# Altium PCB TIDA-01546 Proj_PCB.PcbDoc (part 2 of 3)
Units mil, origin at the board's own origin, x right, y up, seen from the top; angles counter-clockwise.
Board outline 2500 x 2000 mil, 2 copper layers (Top Layer, Bottom Layer), stack 62 mil thick; 176 components, 113 nets, 564 pads, 250 vias.
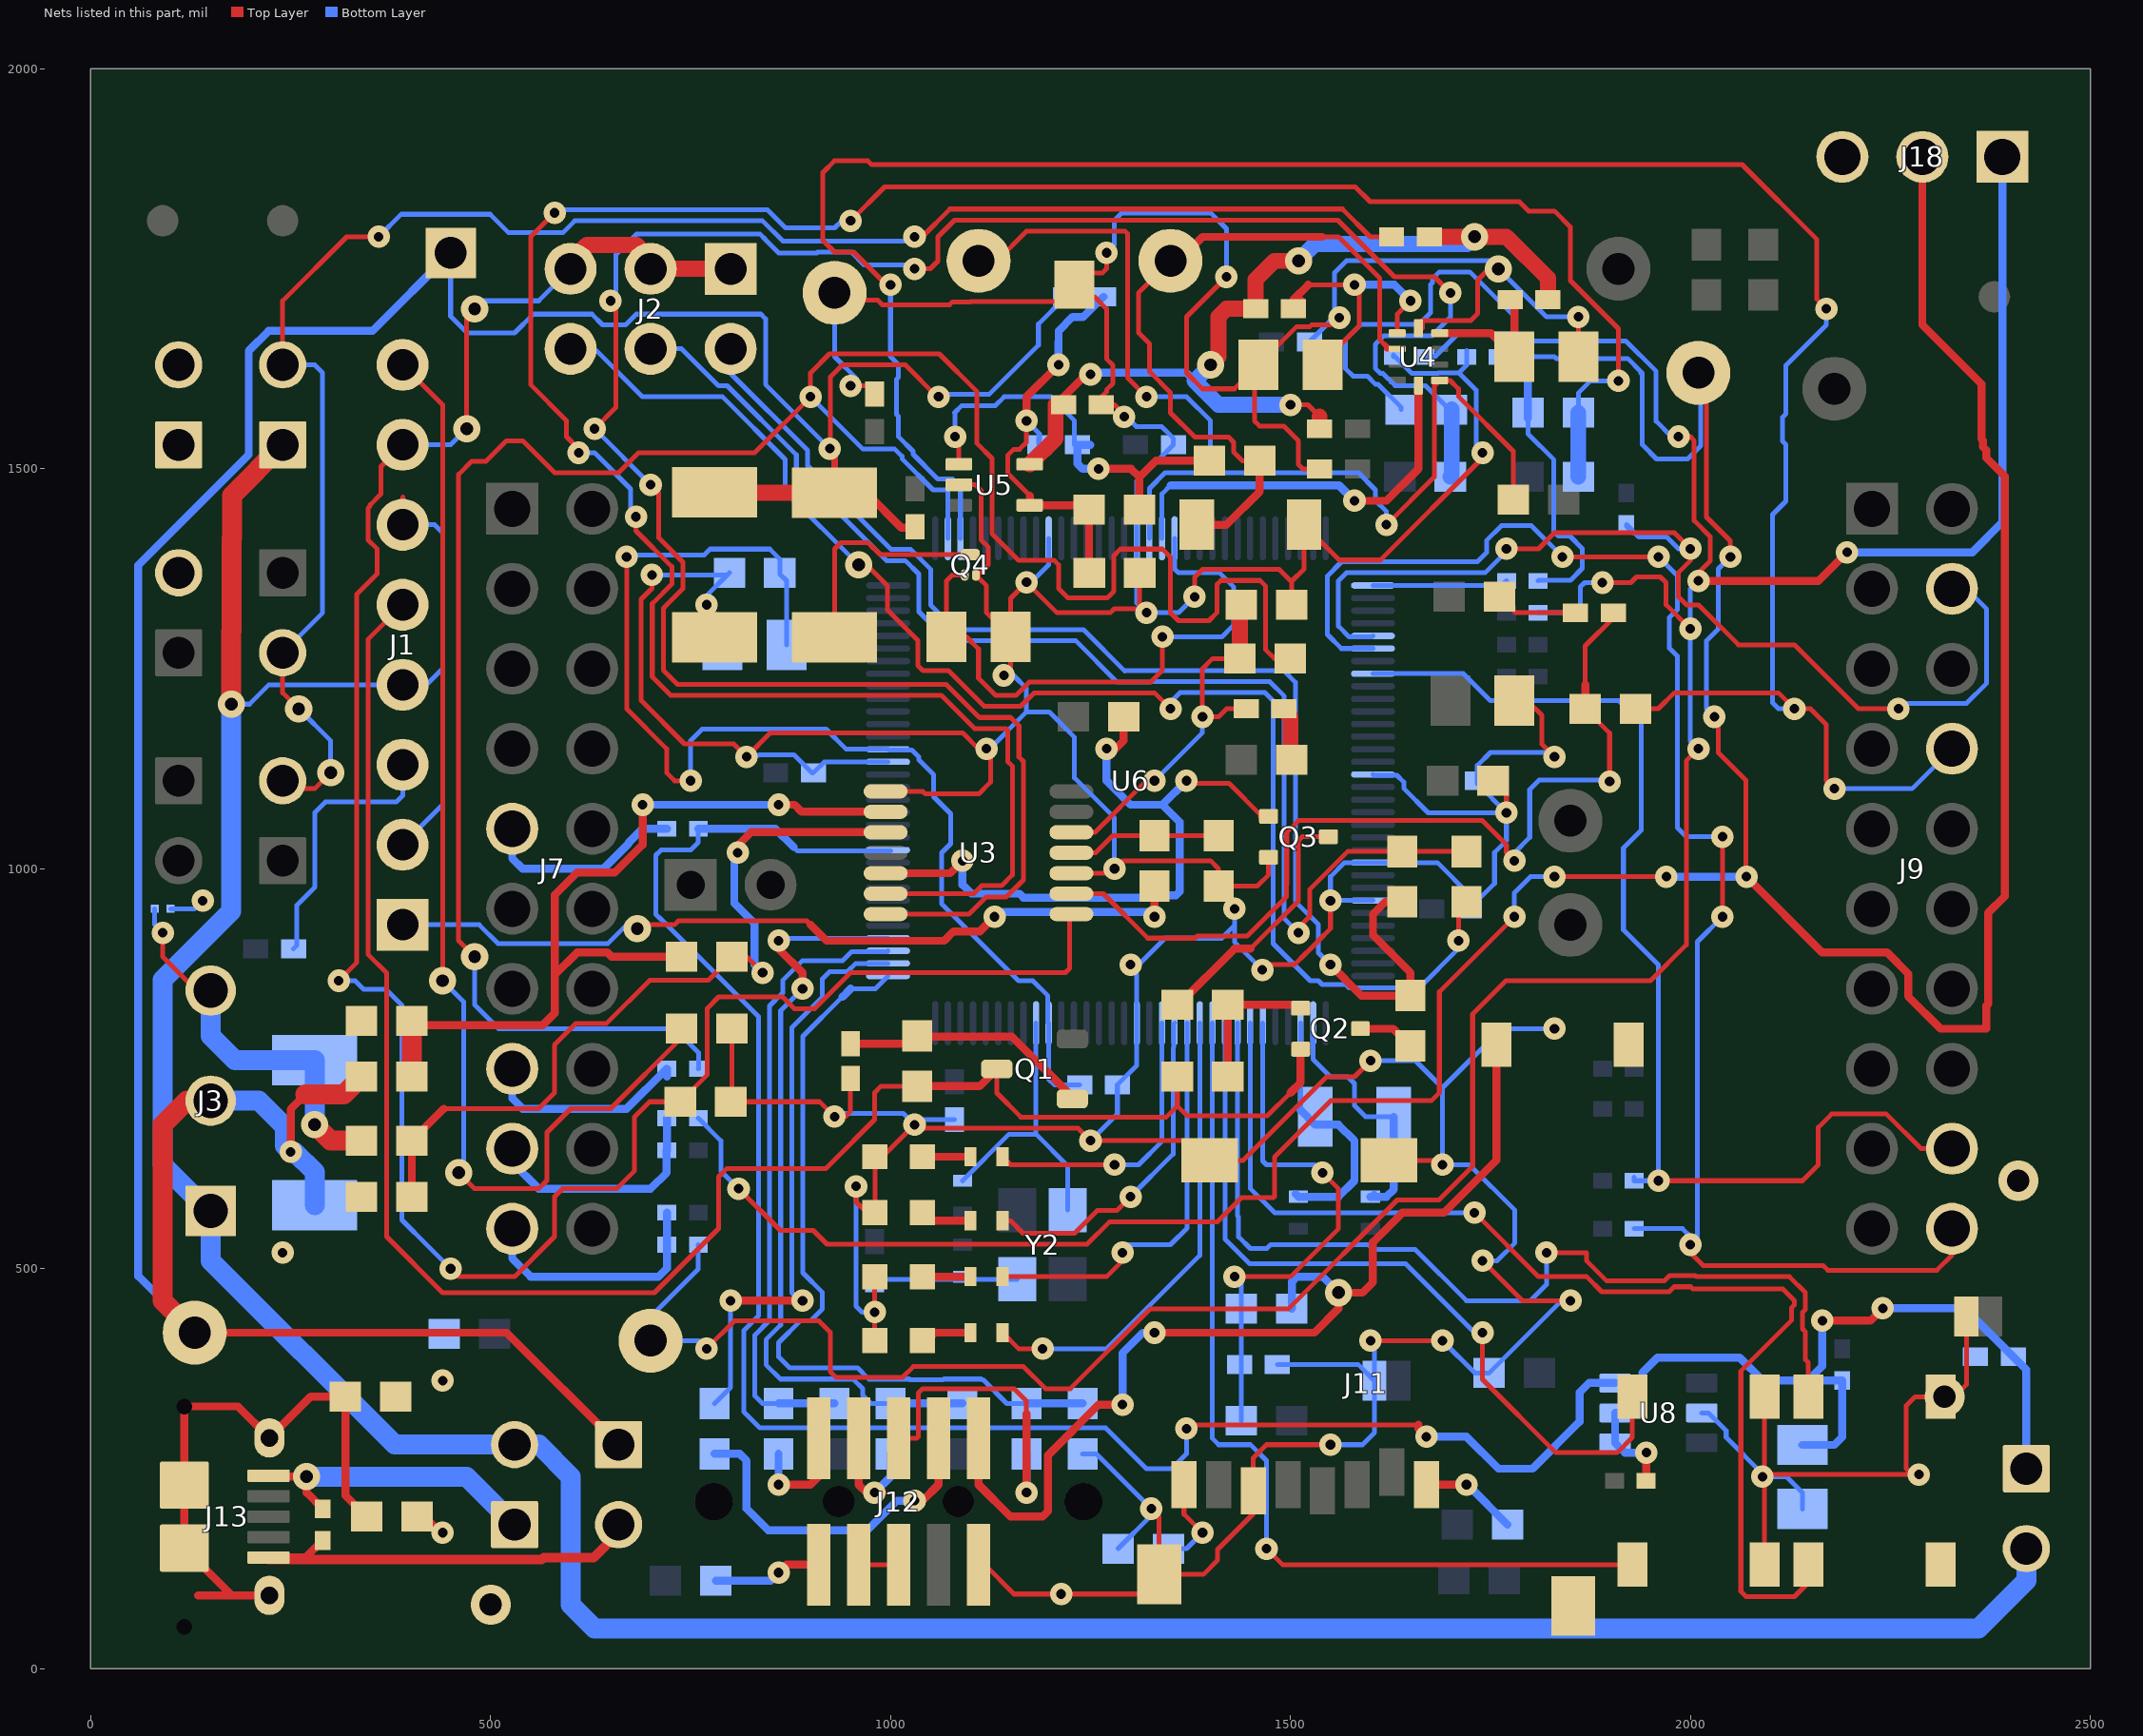
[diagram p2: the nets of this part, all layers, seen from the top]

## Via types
v1: diameter 28, hole 12, Top Layer to Bottom Layer, 217 vias
v2: diameter 34, hole 16, Top Layer to Bottom Layer, 30 vias
v3: diameter 50, hole 28, Top Layer to Bottom Layer, 3 vias

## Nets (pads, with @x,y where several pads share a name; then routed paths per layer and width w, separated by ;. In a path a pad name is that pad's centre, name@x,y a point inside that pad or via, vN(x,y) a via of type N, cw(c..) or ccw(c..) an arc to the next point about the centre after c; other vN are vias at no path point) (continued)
AGND: C8.1 C10.1 NT2.1 R35.2 R77.1 U4.10 | length 1552.6
  Top Layer w6: NT2.1@1230,1745 1265,1745 1270,1750 v1(1270,1770) v1@1265,1765 ; v1(1420,1740) 1370,1690 1370,1620 1390,1600 1430,1600 C8.1@1455.13,1625.13 ; R35.2@1536.38,1500 1515.17,1500 1510,1505.17 1510,1533.2 1509.76,1533.44 1509.76,1535.12 1491.43,1553.45 1461.37,1553.45 1455.13,1559.7 C8.1@1455.13,1625.13 ; v1(1561.14,1688.86) 1560,1690 1550.18,1680.18 1526.74,1680.18 1523.87,1677.32 1507.32,1677.32 C8.1@1460,1630 C8.1@1455.13,1625.13 ; U4.10@1660,1675.93 1664.87,1675.93 1664.87,1685.4 1725.4,1685.4 1734.07,1694.07 1734.07,1735.93 1748.13,1750 v2(1760,1750) ; C10.1@1860,1640 v1(1860,1690)
  Bottom Layer w6: v1(1270,1770) 1280,1780 1280,1810.87 1289.13,1820 1400,1820 1420,1800 v1(1420,1740) ; R77.1@1523.62,1658.52 1553.96,1688.86 v1(1561.14,1688.86) 1555.13,1694.87 1555.13,1745.13 1570,1760 1750,1760 v2(1760,1750) 1820,1690 v1(1860,1690)
ALERT: R26.2 TP10.1 U4.6 U6.18 | length 1390
  Top Layer w6: TP10.1@1110,1760 1133,1760 1170,1797 1293,1797 1296.13,1793.87 1296.13,1613.87 v1(1320,1590) ; v1(1620,1430) 1680,1490 1680,1603.9 U4.6@1686.57,1610.47 1699.53,1610.47 1710,1600 1710,1590.38 1778.5,1521.88 R26.2@1778.5,1461.46 R26.2@1780,1462.95
  Bottom Layer w6: v1(1320,1590) 1370,1590 1400,1560 1400,1495.17 ; U6.18@1323.62,1413.15 1323.62,1475.36 1343.42,1495.17 1400,1495.17 ; v1(1620,1430) 1620,1446.72 1606.29,1460.43 1606.29,1473.71 1584.83,1495.17 1400,1495.17
AVDD: C9.1 R24.2 R27.2 R34.1 R58.2 U5.5 | length 1144.2
  Top Layer w6: v1(1500,1580) 1521.65,1580 1536.38,1565.28
  Top Layer w10: C9.1@1206.38,1580 1244.5,1618.13 v1(1250,1618.13)
  Top Layer w20: U5.5@1173.98,1505.59 1206.38,1537.99 C9.1@1206.38,1580 ; v2(1400,1630) 1410,1640 1410,1690 1420,1700 R58.2@1456.38,1700 1456.38,1736.38 1480,1760 v2(1510,1760) ; R34.1@1536.38,1550 1536.38,1565.28 ; R24.2@1673.62,1790 v2(1730,1790) 1770,1790 1821.85,1738.15 R27.2@1821.85,1711.34
  Bottom Layer w10: v1(1250,1618.13) 1252.13,1620.25 1369.75,1620.25 1380,1610
  Bottom Layer w20: v2(1400,1630) 1380,1610 1410,1580 v1(1500,1580) ; v2(1510,1760) 1530.87,1780.87 1720.87,1780.87 v2(1730,1790)
B\U\S\Y/RDY: U4.5 U6.19 | length 509.2
  Top Layer w10: v1(1580,1460) 1620,1460 1660,1500 U4.5@1660,1604.07
  Bottom Layer w6: U6.19@1339.37,1413.15 1339.37,1468.66 1350,1479.29
  Bottom Layer w10: 1350,1479.29 1560.71,1479.29 v1(1580,1460)
BAT+: J1.2 J1.4 J1.6 J3.1 J4.1 J14.2 J20.2 | length 4532
  Top Layer w6: J4.1@230,1530 J4.1@240,1530 ; J1.6@390,1430 390,1464.42
  Top Layer w25: J3.1@150,560 J3.1@150,572.2 ; v2(175.75,1205.75) 175.75,1296.82 176.22,1297.29 176.22,1412.9 176.63,1413.31 176.63,1466.63 J4.1@240,1530
  Bottom Layer w6: v2(175.75,1205.75) 198.62,1205.75 222.86,1230 223.27,1229.6 390,1229.6 J1.4@390,1230 420,1230 440,1250 ; J1.2@390,1030 440,1080 440,1250 ; J1.6@390,1430 430,1430 440,1420 440,1250
  Bottom Layer w25: v2(175.75,1205.75) 175.75,946.9 90,861.15 90,630 147.8,572.2 J3.1@150,572.2 150,510 380,280 J14.2@530,280 560,280 600,240 600,80 630,50 2360,50 2420,110 J20.2@2420,150
BAT-: J3.2 J8.1 J15.1 R17.1 R19.1 R32.1 R33.1 R90.1 R93.1 TP8.1 | length 4427.8
  Top Layer w6: v1(924,1525.13) 924.87,1526 924.87,1614.87 939.74,1629.74 1018.59,1629.74 1058.34,1590 v1(1060,1590)
  Top Layer w8: R33.1@930,1470.24 v1@930,1520.32
  Top Layer w10: TP8.1@130,420 520,420 J15.1@660,280 ; v1(250,646.03) 250,699.26 268.61,717.87 ; R33.1@930,1470 969.94,1470 1013.56,1426.38 R90.1@1020,1426.38
  Top Layer w20: R32.1@780,1470.55 780.55,1470 R33.1@930,1470
  Top Layer w25: TP8.1@130,420 90,460 90,680 120,710 J3.2@150,710 J3.2@150,700 ; 268.61,717.87 316.38,717.87 R17.1@338.5,740
  Bottom Layer w6: J8.1@450,1770 450,1690.58 470.63,1669.95 529.91,1669.95 553.31,1693.35 626.65,1693.35 640,1680 668.69,1680 682.04,1693.35 837.83,1693.35 843.66,1687.52 843.66,1605.46 v1(924,1525.13) ; v1(1060,1590) 1063,1593 1123.18,1593 1184.87,1654.7 1184.87,1681 R93.1@1218.88,1715
  Bottom Layer w10: TP8.1@130,420 59.45,490.55 59.45,1379.45 197.6,1517.6 197.6,1647.56 222.44,1672.4 352.4,1672.4 J8.1@450,1770
  Bottom Layer w25: J3.2@150,710 210,710 242.63,677.37 242.63,653.41 v1(250,646.03) 254.79,646.03 280,620.82 R19.1@280,579.45
BQ_ALERT: J9.8 R16.2 U6.3 | length 3009.5
  Top Layer w6: v1(1000,1730) 994.82,1730 953.95,1770.87 930,1770.87 915.26,1785.62 915.26,1849.44 915.13,1849.57 915.13,1870.3 929.7,1884.87 971.59,1884.87 976.22,1880.24 2064.66,1880.24 2157.75,1787.15 2157.75,1712.25 v1(2170,1700) ; R16.2@1931.5,1200 1960,1200 1980,1220 2110,1220 v1(2130,1200) 2150,1200 2170,1180 2170,1110 v1(2180,1100)
  Bottom Layer w6: v1(1000,1730) 1000,1640 1010,1630 1010,1614.42 1007.38,1611.8 1007.38,1568.2 1010,1565.58 1010,1540 1028.17,1521.83 1028.17,1518.2 1058.99,1487.38 1077.43,1487.38 1087.4,1477.4 U6.3@1087.4,1413.15 ; v1(2130,1200) 2110,1200 2102.62,1207.38 2102.62,1442.62 2119.26,1459.26 2119.26,1530.36 2115.13,1534.49 2115.13,1564.44 2119.26,1568.58 2119.26,1629.26 2170,1680 v1(2170,1700) ; v1(2180,1100) 2277,1100 J9.8@2327,1150
BQ_SCL: J18.2 R7.2 R37.1 R46.1 TP5.1 U2.1 | length 4751.6
  Top Layer w6: v1(810,600) 862.25,547.75 903.38,547.75 920.63,530.5 1245.7,530.5 1273.95,558.75 1408.75,558.75 1438.75,588.75 1478.75,588.75 1480,590 1480,639.62 1550.38,710 1676.13,710 1686.13,720 1686.13,846.13 v1(1780,940) ; v1(1830,990) v1(1970,990) ; TP5.1@2010,1620 2020,1610 2020,1439.62 2049.62,1410 2049.62,1390.38 v1(2050,1390) ; v1(2030,1190) 2034.87,1185.13 2034.87,1145.13 2069.24,1110.76 v1@2069.24,990
  Top Layer w10: v1@2069.24,990 v1(2070,990) 2164.65,895.35 2245.79,895.35 2272.35,868.79 2272.35,840.51 2312.86,800 2370,800 2370,828.86 2372.35,831.21 2372.35,944.91 2392.87,965.42 2392.87,1490.76 2370,1513.64 2370,1523.2 2365.69,1527.5 2365.69,1535.45 2363.78,1537.36 2363.78,1606.22 2290,1680 J18.2@2290,1890
  Bottom Layer w6: R46.1@759.68,688.19 787.87,660 787.87,622.13 v1(810,600) ; U2.1@1759.68,1640 1770,1640 1830,1640 1832.13,1637.87 1921.55,1637.87 1937.87,1621.55 ; v1(1780,940) 1780,970 1800,990 v1(1830,990) ; R7.2@1796.85,1563.15 1796.85,1543.76 1829.28,1511.33 1829.28,1421.49 1834.87,1415.9 1849.28,1415.9 1864.87,1400.3 1864.87,1375.4 1850,1360.52 1810.21,1360.52 R37.1@1809.68,1360 ; 1937.87,1619.42 1937.87,1621.55 ; TP5.1@2010,1620 2012.87,1620 2012.87,1528.68 1996.55,1512.35 1957.65,1512.35 1940,1530 1940,1619.42 1937.87,1621.55 ; v1(2030,1190) 2020,1200 2020,1284.82 2034.87,1299.7 2034.87,1374.87 v1(2050,1390)
  Bottom Layer w10: U2.1@1770,1640 1796.85,1613.15 R7.2@1796.85,1570 R7.2@1796.85,1563.15 ; v1(1970,990) v1@2060,990
BQ_SDA: J18.1 R6.2 R38.2 R47.1 TP4.1 U1.1 | length 4552.6
  Top Layer w6: v1(770,400) 804.87,434.87 910.3,434.87 924.87,420.3 924.87,371.06 932.06,363.87 1014.63,363.87 1028.36,377.6 1166.07,377.6 1193.67,350 1224.82,350 1324.82,450 1497.55,450 1633.42,585.87 1685.42,585.87 1727.75,628.2 1727.75,818.43 1769.31,860 1950,860 1994.87,904.87 1994.87,1134.87 v1(2010,1150) ; v1(1890,1357.7) 1925.4,1357.7 1932.58,1364.87 1962.35,1364.87 1969.65,1357.58 1969.65,1329.9 1999.54,1300 v1(2000,1300) ; v1(1985,1540.23) 1999.77,1540.23 2004.71,1535.29 2004.71,1435.29 2024.87,1415.13 2024.87,1384.82 2010,1369.95 v1(2010,1360)
  Top Layer w10: v1(2010,1360) 2160.13,1360 v1(2195.78,1395.65)
  Bottom Layer w6: R47.1@759.68,530 759.68,499.68 700,440 TP4.1@700,410 760,410 v1(770,400) ; R6.2@1638.5,1574 1638.5,1576.67 1609.77,1605.41 1606.46,1605.41 1596,1615.87 1578.13,1615.87 1568.54,1625.46 1568.54,1661.08 1587.82,1680.35 1660.35,1680.35 1675.13,1695.13 1675.13,1730.3 1677.41,1732.59 1677.41,1737.41 1686.13,1746.13 1724.1,1746.13 1780,1690.23 1780,1668.54 ; U1.1@1668.03,1640 1680.51,1640 1709.06,1668.54 1780,1668.54 ; R38.2@1809.69,1320 1856.38,1320 1862.28,1325.91 1862.28,1352.28 1867.7,1357.7 v1(1890,1357.7) ; v1(1985,1540.23) 1976.45,1540.23 1957.13,1559.55 1957.13,1621.91 1919.04,1660 1788.54,1660 1780,1668.54 ; v1(2010,1150) 2000,1160 v1(2000,1300) 2000,1350 v1(2010,1360)
  Bottom Layer w10: v1(2195.78,1395.65) 2352.66,1395.65 2390,1432.98 J18.1@2390,1890
BUT_S1: S1.2 U6.74 | length 1173.8
  Top Layer w6: v1(1470,150) 1490,130 S1.2@1927.32,130
  Bottom Layer w6: U6.74@1402.36,806.85 1402.36,287.8 1410.16,280 1450,280 1470,260 v1(1470,150)
BUT_S2: S2.2 U6.73 | length 982.7
  Top Layer w6: v1(1740,420) 1740,361.65 1831.65,270 1908.4,270 1927.32,288.93 S2.2@1927.32,340
  Bottom Layer w6: U6.73@1418.11,806.85 1418.11,537.07 1449.05,506.13 1643.87,506.13 1730,420 v1(1740,420)
BUT_S3: S3.2 U6.72 | length 1228
  Top Layer w6: v1(1820,520) 1870,520 1870,510 1895,485 1967.7,485 1973.95,491.25 2006.05,491.25 2007.3,490 2123.87,490 2143.87,470 2143.87,449.05 2140.13,445.3 2140.13,424.7 2143.87,420.95 2143.87,386.13 2147.32,382.68 S3.2@2147.32,340
  Bottom Layer w6: U6.72@1433.86,806.85 1433.86,566.14 1435.13,564.87 1435.13,539.7 1449.7,525.13 1470.3,525.13 1475.18,530 1597.55,530 1603.43,524.13 1655.87,524.13 1720,460 1800,460 1820,480 v1(1820,520)
BUT_S4: S4.2 U6.71 | length 1458.2
  Top Layer w6: v1(1730,570) 1810,490 1870.38,490 1889.25,471.13 1973.45,471.13 1979.7,477.37 2000.3,477.37 2002.8,474.87 2115.13,474.87 2130,460 2130,454.8 2126.25,451.05 2126.25,435.21 2063.1,372.06 2063.1,96.47 2069.58,90 2130,90 2147.32,107.32 S4.2@2147.32,130
  Bottom Layer w6: U6.71@1449.61,806.85 1449.61,600.39 1480,570 v1(1730,570)
D\E\B\U\G\_\R\E\S\E\T\: J12.P10 R70.2 RESET1.2 | length 1273.4
  Top Layer w10: J12.P10@1110,287.8 1110,230 1150,190 1190,190 1196.87,196.87 1196.87,266.87 1260,330 v1(1290,330) ; v1(1330,420) 1530,420 1560,450 v2(1560,470) 1590,470 1603.13,483.13 1603.13,533.13 1640,570 1691.99,570 1757.32,635.33 RESET1.2@1757.32,780
  Bottom Layer w10: v1(1290,330) 1290,394.4 1315.6,420 v1(1330,420) ; R70.2@1501.5,450 1501.89,450.39 1501.89,483.7 1508.19,490 1540,490 v2(1560,470)
DEBUG_TCK: R43.2 R50.2 U6.100 | length 970.2
  Top Layer w10: v1(860,910) 860,900 890,870 v1(890,850)
  Bottom Layer w6: v1(860,910) 863.15,913.15 U6.100@996.85,913.15 ; v1(890,850) 862.62,822.62 862.62,429.65 844.31,411.33 844.31,380 862.25,362.06 953.14,362.06 965.19,350 965.19,341.61 975.3,331.5 R50.2@1000,331.5
  Bottom Layer w10: R50.2@1000,331.5 R43.2@1090,331.5
DEBUG_TDI: R53.2 U6.98 | length 742.7
  Top Layer w10: v1(800,460) v1(890,460)
  Bottom Layer w6: R53.2@780,331.5 800,351.5 v1(800,460) ; v1(890,460) 886.5,460 876.5,470 876.5,801.32 914.87,839.7 914.87,862.42 923.7,871.25 946.05,871.25 956.45,881.65 U6.98@996.85,881.65
DEBUG_TDO: R51.2 R56.1 U6.97 | length 983.5
  Bottom Layer w6: 940,840 890.37,790.37 890.37,494.81 914.87,470.3 914.87,449.7 900.3,435.13 887.72,435.13 860,407.4 860,390 874.07,375.93 958.89,375.93 972.76,362.06 1023.2,362.06 1024.24,361.02 1065.76,361.02 1066.8,362.06 1113.2,362.06 1114.24,361.02 1115.78,361.02 1145.3,331.5 R51.2@1170,331.5 ; 950,850 980.94,850 U6.97@996.85,865.91
  Bottom Layer w10: 940,840 950,850 ; R51.2@1170,331.5 R56.1@1240,331.5
DEBUG_TMS: R42.2 R49.2 U6.99 | length 784.2
  Bottom Layer w6: R49.2@859.93,331.5 839.89,331.5 830.43,340.96 830.43,417.08 848.75,435.39 848.75,828.37 865.13,844.75 865.13,860.3 889.95,885.13 940.3,885.13 951.64,896.46 995.91,896.46 U6.99@996.85,897.4
  Bottom Layer w10: R49.2@859.93,331.5 R42.2@929.93,331.5
GE: R22.2 R52.1 U6.2 | length 2930.7
  Top Layer w6: v2@483.65,893.65 v2(480,890) 460,910 460,1493 476.43,1509.43 494.25,1509.43 519.7,1534.87 540.3,1534.87 580.05,1495.13 660,1495.13 684.87,1520 830,1520 v1(900,1590) 900,1620 923.62,1643.62 1060.98,1643.62 1108.13,1596.47 1108.13,1531.72 1126.87,1512.97 1126.87,1418.72 1160,1385.59 1204.41,1385.59 1210,1380 1210,1350.43 1221.69,1338.75 1271.02,1338.75 1279.06,1346.8 1279.06,1391.33 1287.31,1399.57 1339.98,1399.57 1350,1389.56 1350,1320 1360,1310 1397.94,1310 1407.94,1320 1407.94,1355.19 1413.09,1360.34 1461.93,1360.34 1469.06,1353.2 1469.06,1273.62 1480,1262.68 R22.2@1499.84,1262.68
  Bottom Layer w6: v2(480,890) 480,830 510,800 730,800 760,770 760,750.32 R52.1@759.68,750 ; v1(900,1590) 965,1525 1004.84,1525 1014.13,1515.71 1014.29,1515.71 1014.29,1512.46 1053.24,1473.5 1071.65,1473.5 U6.2@1071.65,1413.15
GND: C1.2 C2.1 C4.1 C5.1 C6.1 C7.1 C9.2 C11.1 C13.1 C14.1 C15.1 C16.1 C17.1 C18.1 C19.1 C22.1 C23.1 C24.1 C27.1 D1.2 J10.2 J11.6 J11.S1 J11.S2 J11.S3 J11.S4 J12.P3 J12.P5 J12.P9 J17.1 J17.2 J18.3 LED1.2 LED2.2 LED3.2 LED4.2 NT1.2 NT2.2 NT3.2 NT4.1 Q3.2 Q4.2 R9.2 R23.2 R28.1 R32.2 R36.2 R56.2 R67.2 R71.2 R74.2 R92.1 R94.1 R95.1 RESET1.1 S1.1 S2.1 S3.1 S4.1 TP3.1 U1.2 U2.2 U3.3 U3.8 U5.2 U6.10 U6.17 U6.48 U6.55 U6.58 U6.80 U6.114 U8.2 | length 10875.4
  Top Layer w6: R74.2@420,190 v1(440,170) ; v1(701.75,1367.31) 701.75,1350.65 689.26,1338.16 689.26,1337.97 688.23,1336.94 688.23,1222.1 688,1221.87 688,1210.38 742.25,1156.13 803.87,1156.13 v1(820,1140) 849.95,1169.95 1090.05,1169.95 1110,1150 v1(1120,1150) 1124.87,1145.13 1124.87,1108.11 1110.3,1093.54 1043.54,1093.54 1040.32,1096.76 U3.8@993.85,1096.76 ; v1@764.49,1335.43 v1@769.92,1330 ; v1(770,1330) v1@769.92,1330 ; R32.2@780,1289.45 780,1319.92 v1@769.92,1330 ; R9.2@801.5,800 801.5,710 C1.2@800.2,708.7 911.3,708.7 v1(930,690) 943.24,690 950,696.76 D1.2@950,738.03 ; TP3.1@930,1720 960,1720 969.13,1710.87 983.95,1710.87 989.7,1705.13 1073.76,1705.13 1077.38,1708.75 1099.62,1708.75 1100,1709.13 1224.13,1709.13 NT2.2@1230,1715 1255,1715 1270,1700 1270,1637.55 1277.87,1629.67 1277.87,1606.58 1270,1598.71 1270,1596.38 1253.62,1580 1280,1580 1292.11,1567.89 v1(1292.11,1565) ; v1(950,1603.62) 970,1603.62 R92.1@980,1593.62 ; v1(956.85,603) 956.85,583.6 970.45,570 LED2.2@980.47,570 LED1.2@980.47,640 990,640 v1(1030,680) 1034.28,675.72 1234.28,675.72 v1(1250,660) 1374.25,660 J11.S3@1398.74,635.51 1440.87,635.51 1545.35,740 1580,740 v1(1600,760) ; J12.P3@960,130 J12.P5@1010,130 ; LED4.2@980.47,410 980.17,410.3 v1(980.17,445.63) 980.17,489.7 LED3.2@980.47,490 ; U5.2@1085.39,1480 1106.16,1480 1113,1473.16 1113,1411.26 1122.37,1401.89 1122.37,1380.09 1109.49,1367.2 1109.49,1364.29 1120,1353.78 1120,1320 R36.2@1150,1290 ; J12.P9@1110,130 1117.64,130 1154.35,93.28 v1(1213.22,93.28) 1311.24,93.28 J11.S2@1335.75,117.8 ; v1@1150,1250 R36.2@1150,1290 ; U3.3@1226.13,994.4 1274.4,994.4 v1(1280,1000) 1290,1010 1400,1010 1410,1000 C2.1@1410,978.5 ; v1@1311.5,1328.5 R28.1@1311.5,1370 ; v1(1320,1320) 1315.13,1324.87 1279.7,1324.87 1274.82,1320 1208.03,1320 v1(1170,1358.03) 1150,1338.03 R36.2@1150,1290 ; v1(1325.9,200) 1335.75,190.15 1335.75,122.8 1340.75,117.8 1391.07,117.8 1408.88,135.61 1408.88,148.88 1453.46,193.46 J11.6@1453.46,222.13 1453.46,263.46 1470,280 v1(1550,280) ; v1(1380,1340) 1380,1364.34 1389.87,1374.22 1485.78,1374.22 1500.65,1359.35 1501.5,1359.35 ; v1@1431.02,957.48 C2.1@1410,978.5 ; v1(1464.83,873.53) 1464.83,874.83 1470,880 1504.82,880 1519.95,895.13 1520.3,895.13 1534.87,909.7 1534.87,910.05 1550,925.18 v1(1550,960) ; Q3.2@1472.6,1014.41 1472.6,992.36 1458.74,978.5 C2.1@1410,978.5 ; R23.2@1501.5,1330 1501.5,1359.35 ; v1(1600,410) v1(1690,410) ; J11.S4@1623.15,635.51 1684.49,635.51 v1(1690,630) ; v1(1740,510) 1790,460 v1(1850,460) ; v1(1740,1520) 1740,1513.42 1612.51,1385.93 1561,1385.93 C11.1@1516.93,1430 1516.93,1374.78 1501.5,1359.35 ; C7.1@1753.31,1110 1770,1093.31 v1(1770,1070) ; C4.1@1780,1210 1796.13,1210 1814.43,1191.69 1814.43,1155.57 v1(1830,1140) ; S1.1@2092.68,130 2092.68,237.32 v1(2090,240) v1@2092.68,242.68 ; S2.1@2092.68,340 v1@2092.68,242.68 ; v1(2285.56,242.68) v1@2277.32,242.68 ; NT4.1@2345,440 2345,355 2330,340 S3.1@2312.68,340 2281.07,340 2270,328.93 2270,250 v1@2277.32,242.68 ; v1@2092.68,242.68 v1@2277.32,242.68
  Bottom Layer w6: NT1.2@100,950 130,950 v1(140,960) ; v1(701.75,1367.31) C22.1@795.81,1367.31 ; C23.1@790,1280 770,1300 v1(770,1330) 770,1341.5 C22.1@795.81,1367.31 ; C22.1@798.5,1370 C22.1@795.81,1367.31 ; v1(820,1140) 821.65,1141.65 835.09,1141.65 836.13,1142.68 878.97,1142.68 901.65,1120 C18.1@903.62,1120 917.24,1133.62 U6.114@996.85,1133.62 ; v1(930,690) 934.12,694.12 1015.88,694.12 v1(1030,680) 1036.38,686.38 C17.1@1080,686.38 ; TP3.1@930,1720 930,1640 958.19,1611.81 v1(950,1603.62) ; v1(956.85,603) 956.85,453.15 964.37,445.63 v1(980.17,445.63) ; v1(1120,1150) 1123.9,1150 1170,1196.1 ; v1(1141.61,1241.76) 1153.79,1241.76 1170,1225.55 1170,1196.1 ; v1(1170,1358.03) 1175.67,1358.03 1197.64,1380 U6.10@1197.64,1413.15 ; R56.2@1240,268.5 1257.4,268.5 v1(1325.9,200) 1325.9,191.5 R67.2@1284.41,150 ; v1(1250,660) 1283.62,693.62 C24.1@1283.62,730 1307.87,754.25 U6.80@1307.87,806.85 1307.87,867.95 v1@1295.82,880 ; v1(1280,1000) 1280,1063.54 1230,1113.54 1230,1164.27 1198.17,1196.1 1170,1196.1 ; v1(1292.11,1565) 1295,1565 1307.32,1552.68 1338.97,1552.68 1353.62,1538.03 C15.1@1353.62,1530 1307.87,1484.25 U6.17@1307.87,1413.15 1307.87,1332.13 v1(1320,1320) 1360,1320 v1(1380,1340) ; v1@1292.89,882.93 v1@1295.82,880 ; v1(1430,950) 1430,929.18 ; v1(1464.83,873.53) 1430,908.35 1430,929.18 ; C13.1@1483.62,380 1585,380 NT3.2@1605,360 ; v1(1550,280) 1590,280 1605,295 NT3.2@1605,360 ; v1@1599.03,759.03 v1(1600,760) 1656.13,760 1690,726.13 ; v1(1600,410) 1605,405 NT3.2@1605,360 ; U6.58@1603.15,960.39 1550.39,960.39 v1(1550,960) 1550,990 1567.64,1007.64 U6.55@1603.15,1007.64 1683.66,1007.64 1723.62,967.68 R71.2@1723.62,950 1755.13,981.5 1755.13,1020.3 1770,1035.18 v1(1770,1070) ; U6.48@1603.15,1117.87 1604.09,1116.94 1632.91,1116.94 1641.58,1108.26 1641.58,1100.66 1672.24,1070 v1(1770,1070) ; U1.2@1628.66,1642.44 U1.2@1628.66,1640 1631,1640 1651.72,1619.28 1684.35,1619.28 1685.06,1620 1710.63,1620 ; v1(1690,410) 1730.32,369.68 C19.1@1748.5,369.68 1838.82,460 v1(1850,460) ; U2.2@1720.32,1648.03 U2.2@1720.32,1640 1720.32,1629.68 1710.63,1620 ; v1(1740,510) 1758.48,510 1780.6,532.13 1780.6,573.13 1723.73,630 v1(1690,630) 1690,726.13 ; v1(1740,1520) 1732.06,1527.94 1732.06,1598.57 1710.63,1620 ; v1(1830,800) 1763.87,800 1690,726.13 ; v1(1830,1140) 1824.5,1145.5 1750,1145.5 1733.62,1129.12 C16.1@1733.62,1110 1733.62,1106.38 v1(1770,1070) ; U8.2@2014.13,319.68 2022.43,319.68 2044.69,297.42 2044.69,289.13 2090,243.82 v1(2090,240) 2120,240 2140,220 C14.1@2140,199.69 ; v1@1295.82,880 v1(1300,880) 1310,880 1343.24,913.24 1414.07,913.24 1430,929.18
  other v1: 440,360 240,520
  other v3: 500,80 2317.68,340 2410,610
GPIO0: J9.4 R57.2 U6.37 | length 1356.4
  Top Layer w6: v1(1770,1400) 1810,1400 1830,1420 1980,1420 v1(2000,1400) 2000,1385.18 1985.13,1370.3 1985.13,1339.87 1995,1330 2010,1330 2060,1280 2130,1280 2210,1200 v1(2260,1200)
  Bottom Layer w6: U6.37@1603.15,1291.1 1602.21,1290.17 1573.39,1290.17 1573.23,1290 1560,1303.23 1560,1360 1570,1370 1743.28,1370 1770,1396.72 v1(1770,1400) ; R57.2@1928.35,1420 1920,1428.35 R57.2@1920,1430.31 1935.44,1414.87 1970.3,1414.87 1985.18,1400 v1(2000,1400) ; v1(2260,1200) 2266.65,1206.65 2344.96,1206.65 2370.35,1232.04 2370.35,1324.65 2345,1350 J9.4@2327,1350
GPIO1: J9.20 R55.2 U6.38 | length 2021.2
  Top Layer w6: v1(1840,1390) v1(1960,1390) ; v1(2000,530) 2000,520 2016.13,503.87 2166.07,503.87 2171.78,498.16 2308.16,498.16 2327,517 J9.20@2327,550 ; v1(2040,940) v1(2040,1040)
  Bottom Layer w6: U6.38@1603.15,1275.35 1563.56,1275.35 1546.13,1292.79 1546.13,1365.75 1555,1374.62 1555,1375 1563.87,1383.87 1733.87,1383.87 1745.13,1395.13 1745.13,1410.3 1763.95,1429.13 1800.87,1429.13 v1(1840,1390) ; R55.2@1929.69,550 1990,550 2000,540 v1(2000,530) 2008.75,538.75 2008.75,908.75 v1(2040,940) ; v1(1960,1390) 1983.65,1366.35 1983.65,1324.03 1973.87,1314.25 1973.87,1275.75 1983.65,1265.97 1983.65,1051.23 1994.87,1040 v1(2040,1040) ; J9.20@2327,550 J9.20@2327,553
GPIO2/_DRDY: J9.18 R54.2 U6.40 | length 1446.5
  Top Layer w6: v1@1963.35,606.65 v1(1960,610) 2140,610 2160,630 2160,676.71 2176.65,693.35 2244.96,693.35 2288.31,650 J9.18@2327,650
  Bottom Layer w6: U6.40@1603.15,1243.86 1716.14,1243.86 1750,1210 1910.38,1210 1938.38,1182 1938.38,1048 1916.26,1025.88 1916.26,923.74 1960,880 v1(1960,610) R54.2@1929.69,610 R54.2@1929.69,614.51
GPIO_PK2: Q4.1 R36.1 U6.20 | length 734.2
  Top Layer w6: Q4.1@1090.78,1367.2 1077.2,1367.2 1070,1360 R36.1@1070,1290 1094.87,1290 1110,1274.87 1110,1238.19 1131.31,1216.88 1156.88,1216.88 1173.45,1233.45 1325.13,1233.45 1340,1248.32 v1(1340,1290)
  Bottom Layer w6: v1(1340,1290) 1414.25,1290 1428.78,1304.52 1428.78,1352.54 1411.32,1370 1360,1370 1355.12,1374.88 U6.20@1355.12,1413.15
I2C_SCL: J7.17 R45.2 R46.2 | length 313.3
  Bottom Layer w10: J7.17@540,650 J7.17@527,650 527,633 560,600 700,600 720,620 720,647.87 R45.2@720.31,648.19 R46.2@720.31,688.19
I2C_SDA: J7.19 R47.2 R48.2 | length 313.8
  Bottom Layer w10: J7.19@527,550 527,513 550,490 710,490 720.31,500.31 R47.2@720.31,530 R48.2@720.31,570
LED1: R64.1 U6.78 | length 363.2
  Top Layer w6: R64.1@1140,640 1150,630 v1(1280,630)
  Bottom Layer w6: v1(1280,630) 1310,630 1339.37,659.37 U6.78@1339.37,806.85
LED2: R65.1 U6.77 | length 425.1
  Top Layer w6: R65.1@1140,560 1150,560 1165.63,544.37 1230,544.37 1258.25,572.62 1282.62,572.62 v1(1300,590)
  Bottom Layer w6: v1(1300,590) 1353.24,643.24 1353.24,776.16 1354.18,777.09 1354.18,805.91 U6.77@1355.12,806.85
LED3: R66.1 U6.76 | length 523.8
  Top Layer w6: R66.1@1140,490 1270,490 1290,510 v1(1290,520)
  Bottom Layer w6: v1(1290,520) 1290,530 1350,530 1370.87,550.87 U6.76@1370.87,806.85
LED4: R68.1 U6.75 | length 593.4
  Top Layer w6: R68.1@1140,420 1160,400 v1(1190,400)
  Bottom Layer w6: v1(1190,400) 1270,400 1386.61,516.61 U6.75@1386.61,806.85
Load_Switch: R44.1 U6.107 U8.6 | length 2336.4
  Top Layer w6: v1(1370,300) 1374.87,304.87 1660,304.87
  Top Layer w10: 1660,304.87 1660,300 v1(1670,290)
  Bottom Layer w6: R44.1@759.68,1050 759.68,1033.06 750,1023.37 713,1023.37 706.63,1017 706.63,943 713,936.63 713.37,936.63 834.87,815.13 834.87,441.14 816.56,422.82 816.56,321.11 836.73,300.94 1269.06,300.94 1320,250 1351.4,250 1370,268.6 v1(1370,300) ; 878.75,1027.24 883.54,1022.45 U6.107@1000,1022.45
  Bottom Layer w10: R44.1@759.68,1050 855.99,1050 878.75,1027.24 ; v1(1670,290) 1720,290 1760,250 1802.72,250 1861.34,308.61 1861.34,345.15 1873.27,357.09 U8.6@1905.87,357.09
NetC1_1: C1.1 J1.7 J2.1 J2.3 J2.5 U3.1 | length 2937.3
  Top Layer w6: v1(310,860) 332.77,882.77 332.77,1343.35 357.87,1368.45 357.87,1400.08 346.65,1411.3 346.65,1450.66 349.34,1453.35 349.34,1454.92 362.87,1468.45 362.87,1502.87 J1.7@390,1530 ; v1(450,500) 460,490 530,490 580,540 580,590 590,600 657.57,600 680,622.43 680,690 698.7,708.7 C1.1@737.2,708.7 770.94,742.43 770.94,825.51 785.13,839.7 865.13,839.7 879.7,825.13 905.13,825.13 950,870 1079.7,870 1100.3,870 1218.51,870 1224.09,875.58 1224.09,943.22 U3.1@1226.13,943.22 ; v2(470,1550) 470,1690 v2(480,1700)
  Top Layer w20: J2.5@600,1730 J2.5@600,1750 600,1760 620,1780 682.49,1780 700,1762.49 J2.3@700,1750 J2.1@800,1750
  Bottom Layer w6: v1(310,860) 330.52,860 341.39,849.13 369.42,849.13 389.13,829.42 389.13,560.87 422.18,527.82 v1(450,500) ; J1.7@390,1530 450,1530 v2(470,1550) ; v2(480,1700) 490,1710 560,1710 J2.5@600,1750
NetC2_2: C2.2 R10.2 U3.4 | length 192.8
  Top Layer w6: U3.4@1226.13,1019.99 1256.32,1019.99 1277.83,1041.5 R10.2@1330,1041.5 C2.2@1410,1041.5
NetC3_1: C3.1 C6.2 R20.2 U3.10 | length 1015.5
  Top Layer w6: 441.5,700 560,700 580,720 580,780 606.65,806.65 644.96,806.65 698.74,860.43 771.92,860.43 C3.1@801.5,890 820,890 v1(840,870)
  Top Layer w10: C6.2@401.5,590 R20.2@401.5,660 441.5,700 ; v1(808.99,1020.13) v1@810,1021.14 ; v1@810,1020 v1@810,1021.14 ; U3.10@993.85,1045.58 825.58,1045.58 810,1030 v1@810,1021.14
  Bottom Layer w10: v1(808.99,1020.13) 804.63,1015.76 804.63,956.84 830,931.47 830,880 v1(840,870)
NetC3_2: C3.2 C5.2 R17.2 U3.9 | length 1082.5
  Top Layer w10: C5.2@401.5,810 401.5,804.65 565.35,804.65 580,819.29 580,867.14 ; v1(690,1080) 690,1030 655.35,995.35 608.21,995.35 580,967.14 580,867.14 ; C3.2@728.5,900 C3.2@738.5,890 651.14,890 645.79,895.35 608.21,895.35 580,867.14 ; v1(860,1080) 880,1080 888.83,1071.17 U3.9@993.85,1071.17
  Top Layer w25: R17.2@401.5,740 C5.2@401.5,804.65
  Bottom Layer w10: v1(690,1080) v1(860,1080)
NetC8_2: C8.2 R58.1 U4.1 | length 376.8
  Top Layer w6: 1522.25,1730 v1(1580,1730) 1586.02,1723.98 1586.02,1678.55 1540,1632.54 C8.2@1540,1630 C8.2@1560,1630 ; U4.1@1633.43,1669.53 1633.43,1693.43 v1(1650,1710)
  Top Layer w10: R58.1@1513.62,1710 R58.1@1503.62,1700 1503.62,1711.37 1522.25,1730
  Bottom Layer w10: v1(1580,1730) 1630,1730 v1(1650,1710)
NetC10_2: C10.2 R27.1 U4.9 | length 179.2
  Top Layer w10: U4.9@1686.57,1669.53 1750.47,1669.53 C10.2@1780,1640 1780,1705.94 R27.1@1774.61,1711.34
NetC11_2: C11.2 R31.2 TP9.1 U4.2 | length 902.1
  Top Layer w6: TP9.1@1350,1760 1310,1720 1310,1670 1323.87,1656.13 1323.87,1621.3 1350,1595.18 1350,1570 1380.43,1539.57 1422.69,1539.57 1429.06,1533.2 1429.06,1520.94 1440,1510 R31.2@1461.5,1510 ; 1540,1790 1560,1790 1611.72,1738.28 1611.72,1661.26 1619.25,1653.73 1620.16,1653.73 1620.16,1649.84 U4.2@1633.43,1649.84
  Top Layer w10: TP9.1@1350,1760 1360,1760 1390,1790 1540,1790 ; C11.2@1383.07,1430 1420,1430 1461.5,1471.5 R31.2@1461.5,1510
NetC12_1: C12.1 U6.66 Y1.1 | length 322.5
  Bottom Layer w6: U6.66@1528.35,806.85 1528.35,761.65 1550,740 1571.5,740 1580,731.5 1580,703.87 1593.87,690 Y1.1@1629.21,690 ; C12.1@1600,590 C12.1@1604.8,594.8
  Bottom Layer w10: C12.1@1600,590 1620,590 1629.21,599.21 Y1.1@1629.21,690
NetC13_2: C13.2 R69.2 R70.1 U6.70 | length 669.9
  Top Layer w6: v1(1430,490) 1500,490 1560,550 1560,600 v1(1540,620)
  Bottom Layer w6: v1@1430,480.58 v1@1430.24,480.34 ; v1(1430,490) 1438.5,481.5 R70.1@1438.5,450 1438.5,377.87 R69.2@1438.5,310 ; U6.70@1465.35,806.85 1465.35,634.65 1470,630 1530,630 v1(1540,620)
NetC14_2: C14.2 J20.1 R75.2 R81.1 R94.2 U8.4 U8.5 | length 1086.5
  Top Layer w10: R81.1@1944.68,235 1945,235.32 v1(1945,270) ; v1(2165,435) 2225.05,435 v1(2240.45,450.4)
  Bottom Layer w10: v1(1945,270) 1918.15,270 U8.4@1905.87,282.28 U8.5@1905.87,319.68 1926.4,319.68 1940,333.29 1940,370 1958.81,388.81 2061.5,388.81 2090,360.31 2147.03,360.31 ; C14.2@2140,279.69 2180,279.68 2190,289.68 R75.2@2190,360.31 2147.03,360.31 ; v1(2165,435) 2165,378.29 2147.03,360.31 ; v1(2240.45,450.4) 2343.22,450.4 R94.2@2403.62,390 2420,373.62 J20.1@2420,250
NetC20_2: C20.2 U6.67 Y1.2 | length 325.3
  Bottom Layer w6: Y1.2@1512.6,698.19 U6.67@1512.6,806.85
  Bottom Layer w10: C20.2@1506.38,593.62 C20.2@1510,590 1560,590 1580,610 1580,660 1560,680 1530.79,680 Y1.2@1512.6,698.19
NetC22_2: C22.2 C23.2 C24.2 U6.87 U6.115 | length 1523.2
  Top Layer w6: v1(670,1390) 670.35,1389.65 670.35,1199.65 720,1150 720,1120 730,1110 v1(750,1110)
  Bottom Layer w6: v1(670,1390) 672.18,1392.18 766.92,1392.18 774.31,1399.57 848.97,1399.57 861.5,1387.05 C22.2@861.5,1370 861.5,1368.5 870,1360 C23.2@870,1280 ; v1(750,1110) 750,1160 764.5,1174.5 919.5,1174.5 944.63,1149.37 U6.115@996.85,1149.37 997.79,1148.43 1026.61,1148.43 1035.28,1139.76 1035.28,1136.31 1053.87,1117.72 1053.87,1090 1075.13,1068.75 1075.13,1031.25 1063.87,1020 1063.87,956.18 1114.87,905.18 1114.87,905.13 1160,860 1177.92,860 1196.7,841.22 1196.7,807.79 U6.87@1197.64,806.85 1197.64,736.97 1204.61,730 C24.2@1236.38,730
NetC25_1: C25.1 U6.88 Y2.3 | length 365.9
  Bottom Layer w6: C25.1@1090,610 1148.11,668.11 1181.89,668.11 ; U6.88@1181.89,806.85 1181.89,668.11 ; Y2.3@1221.5,573.31 1221.5,628.5 1181.89,668.11
NetC26_1: C26.1 R73.2 Y2.1 | length 178.6
  Bottom Layer w6: R73.2@980,486.38 1086.38,486.38 1086.69,486.69 Y2.1@1158.5,486.69
NetC27_2: C27.2 J13.6 J13.7 J13.8 J13.9 J13.10 J13.11 R74.1 | length 750
  Top Layer w10: 134.11,91.57 176.14,91.57 ; J13.7@223.39,91.57 176.14,91.57 ; R74.1@345,190 318.5,216.5 C27.2@318.5,340 274.96,340 J13.6@223.39,288.43 184.02,327.8 J13.8@117.09,327.8 J13.10@117.09,229.37 J13.11@117.09,150.63 176.14,91.57
NetC28_1: C28.1 R25.2 R31.1 U5.1 | length 537.7
  Top Layer w6: v1(1080.79,1540) 1085.39,1544.61 U5.1@1085.39,1505.59
  Top Layer w10: v1(1260,1500) 1300.71,1500 1311.18,1489.53 ; R25.2@1311.18,1448.7 1311.18,1489.53 ; R31.1@1398.5,1510 1331.65,1510 1311.18,1489.53
  Bottom Layer w6: v1(1080.79,1540) 1080.79,1569.21 1080,1570 1089.13,1579.13 1131.07,1579.13 1141.95,1590 1200,1590 1230,1560 C28.1@1230,1530
  Bottom Layer w10: 1250,1530 C28.1@1233.62,1530 1233.62,1506.38 1240,1500 v1(1260,1500)
NetC28_2: C28.2 R25.1 R28.2 R93.2 U5.4 | length 526.7
  Top Layer w6: v1(1170,1560) 1170,1533.15 1161.19,1524.34 1153.89,1524.34 1146.37,1516.82 1146.37,1494.37 1173.98,1466.76 1173.98,1466.02
  Top Layer w10: v1(1170,1560) 1170,1590 v1(1210,1630) ; 1173.98,1466.02 U5.4@1173.98,1454.41 1242.48,1454.41 R25.1@1248.19,1448.7 R28.2@1248.19,1378.7
  Bottom Layer w6: v1(1170,1560) 1186.38,1543.62 C28.2@1186.38,1530 1185,1531.38 C28.2@1185,1539
  Bottom Layer w10: v1(1210,1630) 1210,1658.88 1210.13,1659 1210.13,1672.37 1227.63,1689.87 1241,1689.87 R93.2@1266.12,1715
NetD1_1: D1.1 Q1.1 R1.2 | length 299.1
  Top Layer w10: D1.1@950,781.34 R1.2@1023.58,781.34 ; R1.2@1033.42,791.18 1034.61,790 1151.89,790 Q1.1@1227.24,714.65
NetJ1_1: J1.1 R10.1 | length 1031.4
  Top Layer w6: v2(683.34,925.23) 688.11,930 730,930 734.87,934.87 895.13,934.87 900,930
  Top Layer w10: 900,930 920,910 1067.12,910 1078.87,921.75 1111.75,921.75 v1(1130,940) ; v1(1330,940) R10.1@1330,978.5
  Bottom Layer w6: J1.1@390,930 485.69,930 509.04,906.65 646.65,906.65 670,930 674.77,925.23 v2(683.34,925.23)
  Bottom Layer w10: v1(1130,940) 1135.87,945.87 1324.13,945.87 v1(1330,940)
NetJ1_3: J1.3 R80.2 | length 338.4
  Bottom Layer w6: R80.2@253.62,900 257.87,904.25 257.87,954.65 280.4,977.18 280.4,1070.4 293.31,1083.31 382,1083.31 390,1091.31 J1.3@390,1130
NetJ1_5: J1.5 Q1.3 Q2.2 R1.1 R2.1 | length 2311.9
  Top Layer w6: J1.5@390,1330 346.65,1286.65 346.65,893.02 370,869.66 370,540 440,470 704.82,470 785.13,550.3 785.13,615.13 794.87,624.87 918.82,624.87 953.85,659.9 953.85,660.25 980,686.4 980,720 988.19,728.19 R1.1@1033.42,728.19 ; Q1.3@1132.76,749.69 1132.76,719.68 1162.84,689.6 1344.72,689.6 1358.5,703.39 ; R2.1@1358.5,740 1358.5,703.39 ; 1500,720 1471.02,691.02 1370.87,691.02 1358.5,703.39
  Top Layer w10: R1.1@1033.42,728.19 1111.26,728.19 Q1.3@1132.76,749.69 ; 1500,720 1512.6,732.6 Q2.2@1512.6,774.41
NetJ1_8: J1.8 R9.1 | length 1455.6
  Top Layer w6: J1.8@390,1630 440,1580 v2(440,860) ; v2(460,620) 480,600 560,600 570.35,610.35 570.35,670.35 600,700 650,700 738.5,788.5 R9.1@738.5,800
  Bottom Layer w6: v2(440,860) 466.13,833.87 466.13,626.13 v2(460,620)
NetJ2_2: J2.2 R8.2 R11.1 | length 1586.3
  Top Layer w10: v1(1550,880) 1588.5,841.5 R8.2@1650,841.5 1650,870 1603.15,916.85 1603.15,943.15 1618.5,958.5 R11.1@1640,958.5
  Bottom Layer w6: J2.2@800,1650 800,1619.24 896.13,1523.12 896.13,1503.87 1000.93,1399.07 1025.42,1399.07 1050,1374.49 1050,1329.62 1080.87,1298.75 1241.25,1298.75 1292.68,1247.32 1293.19,1247.84 1479.78,1247.84 1480.3,1247.32 1491.92,1247.32 1506.13,1233.12 1506.13,959.05 1534.87,930.3 1534.87,895.13 v1(1550,880)
NetJ2_4: J2.4 R11.2 R14.2 | length 1590.1
  Top Layer w6: v1(1510,920) 1510,926.51 1523.87,940.38 1523.87,973.87 1571.5,1021.5 R11.2@1640,1021.5 R14.2@1720,1021.5
  Bottom Layer w6: J2.4@700,1650 738.69,1650 784.81,1603.87 795.75,1603.87 882.25,1517.37 882.25,1497.75 994.8,1385.2 1018.38,1385.2 1035.28,1368.29 1035.28,1321.41 1071.82,1284.87 1231.71,1284.87 1283.13,1233.45 1325.13,1233.45 1325.64,1233.96 1474.03,1233.96 1492.25,1215.75 1492.25,937.75 v1(1510,920)
NetJ2_6: J2.6 R14.1 | length 1796.5
  Top Layer w6: v2(960,1380) 970,1380 996.38,1353.62 996.38,1323.2 1034.13,1285.45 1034.13,1254 1040.5,1247.63 1072.37,1247.63 1116.99,1203.01 1162.63,1203.01 1179.2,1219.57 1330.43,1219.57 v1(1350,1200) ; v1(1710,910) 1710,948.5 R14.1@1720,958.5
  Bottom Layer w6: J2.6@600,1650 630,1650 690,1590 790,1590 868.38,1511.62 868.38,1471.62 v2(960,1380) ; v1(1350,1200) 1350,1208.18 1361.91,1220.09 1468.29,1220.09 1478.38,1210 1478.38,906.44 1524.82,860 1534.82,860 1539.7,855.13 1569.36,855.13 1573.39,851.09 1661.09,851.09 1710,900 v1(1710,910)
NetJ3_3: J3.3 NT1.1 R19.2 R20.1 | length 488.5
  Top Layer w6: v1(90,920) 90,890 132.2,847.8 J3.3@150,847.8
  Top Layer w25: v2(280,680) 300,660 R20.1@338.5,660
  Bottom Layer w6: NT1.1@80,950 80,930 v1(90,920)
  Bottom Layer w25: J3.3@150,847.8 150,790.81 180.26,760.55 R19.2@280,760.55 v2(280,680)
NetJ4_2: J4.2 J5.2 J6.2 R24.1 | length 2240.4
  Top Layer w6: J6.2@240,1110 250,1100 280,1100 v2(300,1120) ; J5.2@240,1270 240,1220 v2(260,1200) ; J4.2@240,1630 240,1710 320,1790 v1(360,1790) ; v1(1030,1790) 1039.51,1790 1074.25,1824.75 1564.87,1824.75 1599.62,1790 R24.1@1626.38,1790
  Bottom Layer w6: J5.2@240,1270 290,1320 290,1620 280,1630 J4.2@240,1630 ; v2(260,1200) 300,1160 v2(300,1120) ; v1(360,1790) 388.18,1818.18 499.41,1818.18 522.46,1795.13 590.3,1795.13 605.18,1810 839.96,1810 865.21,1784.75 1024.75,1784.75 v1(1030,1790)
NetJ7_9: J7.9 R44.2 | length 257.1
  Bottom Layer w10: J7.9@527,1050 527,1013 540,1000 641.14,1000 672.35,1031.21 672.35,1032.35 690,1050 R44.2@720.31,1050
NetJ7_15: J7.15 R52.2 | length 270.3
  Bottom Layer w10: J7.15@530,753 J7.15@527,750 527,713 540,700 670,700 720,750 R52.2@720.31,750 R52.2@720.31,740.31
NetJ11_1: J11.1 R62.2 | length 122.2
  Top Layer w10: J11.1@1670,230 v1(1720,230)
  Bottom Layer w10: v1(1720,230) 1721.5,230 R62.2@1771.5,180
NetJ11_8: J11.8 R67.1 | length 120.5
  Top Layer w6: J11.8@1366.85,230 1366.85,193.15 v1(1390,170)
  Bottom Layer w6: R67.1@1347.4,150 1370,150 v1(1390,170)
NetJ12_P1: J12.P1 R41.2 | length 122.6
  Top Layer w10: v1(860,120) 870,130 J12.P1@910,130
  Bottom Layer w10: R41.2@781.5,110 850,110
NetJ12_P2: J12.P2 R49.1 | length 140.4
  Top Layer w10: v1(860,230) 900,230 910,240 J12.P2@910,287.8
  Bottom Layer w10: v1@859.93,230.07 R49.1@859.93,268.5
NetJ12_P4: J12.P4 R50.1 | length 148.7
  Top Layer w10: J12.P4@960,287.8 960,230 970,220 v1(980,220) v1@990,220
  Bottom Layer w10: v1(980,220) 1000,240 R50.1@1000,268.5
NetJ12_P6: J12.P6 R51.1 | length 387
  Top Layer w6: J12.P6@1010,287.8 1032.36,287.8 1034.56,290 1034.56,344.56 1039.85,349.85 1154.57,349.85 1170,334.43 1170,318.7
  Top Layer w10: v1(1170,220) 1170,318.7
  Bottom Layer w10: v1(1170,220) R51.1@1170,268.5
NetJ12_P8: J12.P8 R53.1 | length 436
  Top Layer w10: v1(1030,210) 1040,210 1060,230 J12.P8@1060,287.8
  Bottom Layer w10: R53.1@780,268.5 811.5,268.5 820,260 820,200 846.87,173.13 971.13,173.13 1008.01,210 v1(1030,210)
NetJ13_1: J13.1 J14.1 U10.1 | length 381.5
  Top Layer w10: J13.1@222.4,241.18 223.58,240 v2(270,240) 270,220 290,200 U10.1@290,199.68
  Bottom Layer w25: v2(270,240) 470,240 J14.1@530,180
NetJ13_5: J13.5 J15.2 U10.2 | length 540.2
  Top Layer w10: J13.5@230,138.82 268.5,138.82 U10.2@290,160.32
  Top Layer w12: J13.5@230,138.82 J13.5@222.4,138.82 222.4,136.6 564.06,136.6 566.28,138.82 628.82,138.82 660,170 J15.2@660,180
NetLED1_1: LED1.1 R64.2 | length 60.5
  Top Layer w10: LED1.1@1039.53,640 R64.2@1100,640
NetLED2_1: LED2.1 R65.2 | length 64.6
  Top Layer w10: LED2.1@1039.53,570 1049.53,560 R65.2@1100,560
NetLED3_1: LED3.1 R66.2 | length 60.5
  Top Layer w10: LED3.1@1039.53,490 R66.2@1100,490
NetLED4_1: LED4.1 R68.2 | length 58.4
  Top Layer w10: LED4.1@1045.75,410 1055.75,420 R68.2@1100,420
NetQ2_1: Q2.1 R2.2 R5.1 | length 182.9
  Top Layer w10: R2.2@1421.5,740 R5.1@1421.5,830 1508.19,830 Q2.1@1512.6,825.59
NetQ2_3: Q2.3 R8.1 | length 71.5
  Top Layer w10: Q2.3@1587.4,800 1628.5,800 R8.1@1650,778.5
NetQ3_1: Q3.1 R12.2 U3.12 | length 872.5
  Top Layer w6: v1(1370,1110) 1373.29,1106.71 1423.29,1106.71 Q3.1@1464.41,1065.59
  Top Layer w10: U3.12@993.85,994.4 1074.4,994.4 v1(1090,1010) ; v1(1270,1150) 1281.2,1150 1291.5,1160.3 R12.2@1291.5,1190 ; Q3.1@1464.41,1065.59 Q3.1@1472.6,1065.59
  Bottom Layer w10: v1(1090,1010) 1090,980 1101.19,968.81 1161.19,968.81 1166.01,963.99 1315.98,963.99 1318.87,966.87 1356.87,966.87 1361.4,971.4 1361.4,1058.6 1340,1080 ; v1(1270,1150) 1270,1110 1300,1080 1340,1080 ; v1(1370,1110) 1340,1080
NetQ3_3: Q3.3 R5.2 | length 322.2
  Top Layer w6: 1450,900 1510,960 1510,1035.38 1514.62,1040 Q3.3@1547.4,1040
  Top Layer w10: R5.2@1360,831.5 R5.2@1358.5,830 1360,830 1430,900 1450,900
NetQ4_3: Q4.3 R33.2 | length 290.1
  Top Layer w6: R33.2@930,1289.13 930,1400 937.87,1407.87 971.55,1407.87 979.42,1400 980,1400 987.2,1392.8 Q4.3@1099.68,1392.8
NetR3_2: R3.2 R6.1 U3.14 | length 2973.8
  Top Layer w6: v1(630,1550) 656.65,1576.65 656.65,1703.35 v1(650,1710) ; v1(700,1480) 710,1470 710,1413.85 740.5,1383.36 740.5,1350.16 717.01,1326.67 717.01,1326.48 715.98,1325.45 715.98,1248.11 733.4,1230.69 1069.31,1230.69 1110,1190 1110.38,1190 1111.24,1189.14 1150,1189.14 1160.52,1178.62 1160.52,1139.71 1166.13,1134.1 1166.13,986.13 1144.87,964.87 1119.7,964.87 1098.04,943.22 U3.14@993.85,943.22 ; v1(1030,1750) 1049.56,1750 1059.13,1759.56 1059.13,1790 1080,1810.87 1559.13,1810.87 1630,1740 1680,1740 v1(1700,1720)
  Bottom Layer w6: v1(630,1550) v1(700,1480) ; v1(650,1710) 656.65,1716.65 656.65,1767.96 682.04,1793.35 836.98,1793.35 843.35,1786.98 843.35,1786.65 860,1770 908.05,1770 908.93,1770.87 951.07,1770.87 967.07,1754.87 1025.13,1754.87 v1(1030,1750) ; v1(1700,1720) 1700,1689.84 1676.64,1666.48 1616.95,1666.48 1605.98,1655.51 1605.98,1625.65 1612.35,1619.28 1615.51,1619.28 1630.72,1604.07 1668.63,1604.07 1698.7,1574 R6.1@1701.5,1574
  Bottom Layer w20: R3.2@1699.84,1490 1701.5,1491.65 R6.1@1701.5,1574
NetR4_2: R4.2 R7.1 U3.13 | length 3212.1
  Top Layer w6: v1(580,1820) 550,1790 550,1605.18 594.87,1560.3 594.87,1540.3 610,1525.18 v1(610,1520) ; v1(681.69,1440) 681.69,1422.55 726.62,1377.61 726.62,1355.9 703.13,1332.42 703.13,1332.23 702.1,1331.2 702.1,1240 725.29,1216.82 1063.56,1216.82 1105.12,1175.26 1144.13,1175.26 1146.64,1172.75 1146.64,1133.97 1152.25,1128.36 1152.25,992.25 1138.75,978.75 1113.95,978.75 1104.01,968.81 U3.13@993.85,968.81 ; v1(950,1810) 992.5,1852.5 1581,1852.5 1599.62,1833.87 1786.13,1833.87 1797.75,1822.25 1830,1822.25 1850,1802.25 1850,1735.18 1910,1675.18 v1(1910,1610)
  Bottom Layer w6: v1(580,1820) 583.87,1823.87 846.13,1823.87 868.71,1801.29 930,1801.29 938.71,1810 v1(950,1810) ; v1(610,1520) 630,1520 675.13,1474.87 675.13,1446.56 v1(681.69,1440) ; R7.1@1859.84,1570 1859.84,1594.76 1875.08,1610 v1(1910,1610)
  Bottom Layer w20: R4.2@1859.84,1490 1859.84,1499.9 R7.1@1859.84,1570
NetR13_2: R13.2 R15.1 | length 103.2
  Top Layer w6: R13.2@1761.5,1340 1781.5,1320 R15.1@1856.38,1320
NetR15_2: R15.2 R16.1 U3.2 | length 1153.1
  Top Layer w6: U3.2@1226.13,968.81 1266.01,968.81 1321.58,913.24 1380.79,913.24 1383.42,915.87 1445.87,915.87 1495.13,965.13 1495.13,980.46 1495.28,980.62 1495.28,1045.28 1510.13,1060.13 1739.87,1060.13 1770,1030 1770,1020 v1(1780,1010) ; R16.1@1868.5,1200 1899,1169.5 v1(1899,1109.04) ; 1868.5,1230 1868.5,1278.5 1903.62,1313.62 R15.2@1903.62,1320
  Top Layer w10: R16.1@1868.5,1200 1868.5,1230
  Bottom Layer w6: v1@1780.87,1009.13 v1(1780,1010) 1780,1020 1799.13,1039.13 1799.13,1099.13 1810.87,1110.87 1897.16,1110.87 v1(1899,1109.04)
NetR18_2: R18.2 R21.1 | length 73.3
  Top Layer w20: R21.1@1491.97,1200 1491.97,1198.03 1500,1190 R18.2@1500,1130
NetR21_2: R21.2 R22.1 R23.1 U3.5 | length 476.4
  Top Layer w6: U3.5@1226.13,1045.58 1255.58,1045.58 v1@1320,1110 ; R22.1@1436.85,1262.68 1402.68,1262.68 1390,1250 v1(1390,1190) 1410.35,1190 1420.35,1200 R21.2@1444.72,1200
  Top Layer w20: R23.1@1436.85,1338.68 1436.85,1263.15 R22.1@1440,1260
  Bottom Layer w6: v1(1330,1110) 1390,1170 v1(1390,1190)
NetR37_2: R37.2 U6.33 | length 169.6
  Bottom Layer w6: U6.33@1603.15,1354.09 1764.41,1354.09 R37.2@1770.31,1360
